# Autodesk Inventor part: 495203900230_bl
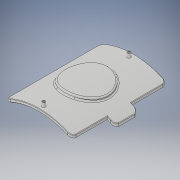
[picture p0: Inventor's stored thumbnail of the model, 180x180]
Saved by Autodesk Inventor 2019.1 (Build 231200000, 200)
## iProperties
Created: 2023-08
Part Number: 495203900230_bl
Material: Generic
Description: Repair Saddle 400-900mm
Document SubType Name: Modeling
Designer: Kirill
Density: 1 g/cm^3
Appearance: Default
Author: Kirill
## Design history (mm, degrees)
derived "49520.ipt"
feature "Solid1::49520.ipt" dims "ScaleForDerivedMember" = 10
tag "TaggingFeature1"
body "Solid1"
other parameters: "d1" = 18 [user parameter], "d2" = 423.9 [user parameter], "d4" = 0 [user parameter], "d5" = 486 [user parameter], "d6" = 282.6 [user parameter], "d8" = 0 [user parameter], "d11" = 0 [user parameter], "d12" = 9.42 [user parameter], "d14" = 493 [user parameter], "d15" = 549 [user parameter], "d16" = 274.5 [user parameter], "d19" = 5 deg [user parameter], "d21" = 14 [user parameter], "d22" = 25.8 [user parameter], "d23" = 0 [user parameter], "d25" = 7 [user parameter], "d27" = 0 [user parameter], "d28" = 471 [user parameter], "d29" = 152.5 [user parameter], "d30" = 0 [user parameter], "d31" = 27 [user parameter], "d32" = 2.7 [user parameter], "B_" = 471 [user parameter], "H_" = 43 [user parameter], "d24" = 14 [user parameter]
